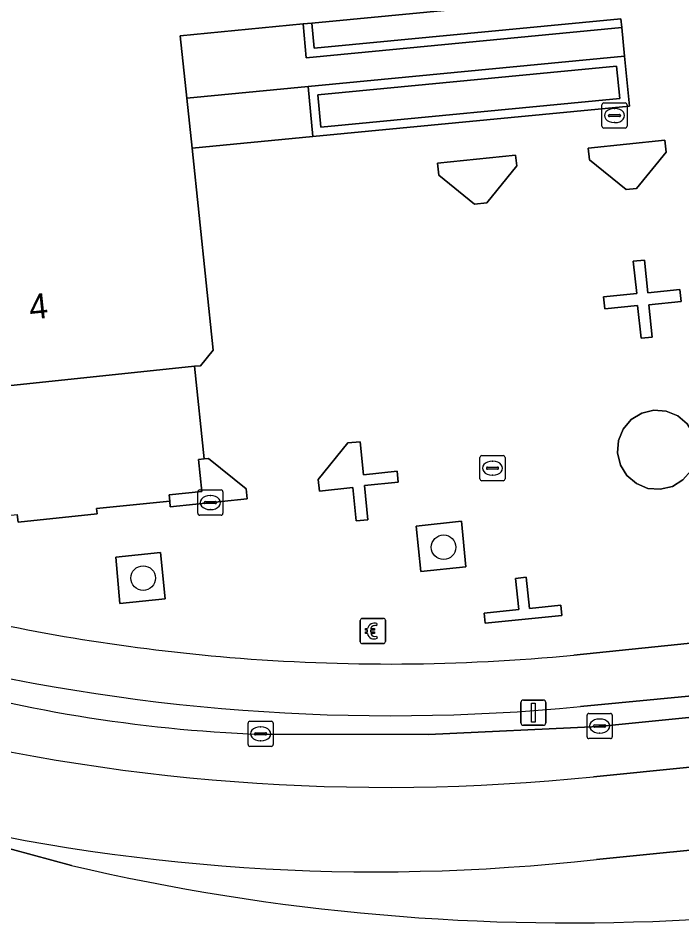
# Model space of a CAD drawing. Extents: x 160675 to 161153, y 383241 to 383714.
# Drawn here: x 160947.05 to 160973.43, y 383561.77 to 383597.73 of the extents above; entities that cross this region are included whole.
import ezdxf

# ---------------------------------------------------------------- set-up
doc = ezdxf.new("R2010")
doc.units = 0
for name, color, linetype in [('IMGEO_Berm_open', 7, 'Continuous'), ('IMGEO_Betaalautomaat', 7, 'Continuous'), ('IMGEO_Boom', 7, 'Continuous'), ('IMGEO_Fietspad_gesloten', 7, 'Continuous'), ('IMGEO_Grasland_overig', 7, 'Continuous'), ('IMGEO_Groenvoorziening', 7, 'Continuous'), ('IMGEO_Kolk', 7, 'Continuous'), ('IMGEO_Lichtmast', 7, 'Continuous'), ('IMGEO_Muur', 7, 'Continuous'), ('IMGEO_OVBaan_gesloten', 7, 'Continuous'), ('IMGEO_Pand', 7, 'Continuous'), ('IMGEO_Pand_nummerreeks', 7, 'Continuous'), ('IMGEO_Parkeervlak_open', 7, 'Continuous'), ('IMGEO_Rijbaan_lokaal_gesloten', 7, 'Continuous'), ('IMGEO_Terreindeel_gesloten', 7, 'Continuous'), ('IMGEO_Voetpad_open', 7, 'Continuous')]:
    doc.layers.add(name, color=color, linetype=linetype)

msp = doc.modelspace()

# ---------------------------------------------------------------- linework, layer by layer
at = {"layer": 'IMGEO_Berm_open'}
for points in [[(160942.181, 383566.161), (160883.368, 383582.463), (160880.432, 383583.23), (160880.388, 383583.018), (160942.127, 383565.955), (160949.177, 383564.05)], [(160977.449, 383568.326), (160978.106, 383568.424), (160978.543, 383571.243), (160969.402, 383570.361)], [(160956.662, 383569.267), (160963.365, 383569.248), (160970.137, 383569.576), (160974.363, 383569.996)], [(160977.669, 383564.976), (160976.009, 383564.886), (160970.034, 383564.292)]]:
    msp.add_lwpolyline(points, dxfattribs=at)
for centre, radius, start, end in [((160961.872, 383648.668), 78.668, 255.91174, 275.49255), ((160958.774, 383626.604), 57.376, 253.39085, 267.89005), ((160961.248, 383641.837), 78.041, 255.85815, 276.46401), ((160968.982, 383648.752), 86.987, 256.83983, 273.19843)]:
    msp.add_arc(centre, radius, start, end, dxfattribs=at)
at = {"layer": 'IMGEO_Betaalautomaat'}
for p, q in [((160960.648, 383572.943), (160960.648, 383573.784)), ((160960.648, 383573.784), (160960.648, 383572.943)), ((160960.723, 383573.867), (160961.564, 383573.867)), ((160961.564, 383573.867), (160960.723, 383573.867)), ((160961.31, 383573.672), (160961.293, 383573.572)), ((160961.647, 383573.793), (160961.647, 383572.952)), ((160961.647, 383572.952), (160961.647, 383573.793)), ((160960.931, 383573.331), (160960.931, 383573.399)), ((160961.052, 383573.399), (160961.052, 383573.331)), ((160961.297, 383573.166), (160961.319, 383573.079)), ((160961.573, 383572.868), (160960.732, 383572.868)), ((160960.732, 383572.868), (160961.573, 383572.868))]:
    msp.add_line(p, q, dxfattribs=at)
for points in [[(160960.931, 383573.399), (160960.862, 383573.399), (160960.862, 383573.468), (160960.941, 383573.468)], [(160960.936, 383573.262), (160960.862, 383573.262), (160960.862, 383573.331), (160960.931, 383573.331)], [(160961.063, 383573.468), (160961.21, 383573.468), (160961.21, 383573.399), (160961.052, 383573.399)], [(160961.052, 383573.331), (160961.21, 383573.331), (160961.21, 383573.262), (160961.066, 383573.262)]]:
    msp.add_lwpolyline(points, dxfattribs=at)
for centre, radius, start, end in [((160960.726, 383573.79), 0.0779, 92.4484, 184.2845), ((160960.726, 383573.79), 0.0779, 92.4484, 184.2845), ((160961.224, 383573.392), 0.293, 73.014, 165.0139), ((160961.57, 383573.79), 0.0779, 2.4484, 94.2845), ((160961.57, 383573.79), 0.0779, 2.4484, 94.2845), ((160961.23, 383573.405), 0.179, 69.3236, 159.5683), ((160960.726, 383572.946), 0.0779, 182.4484, 274.2845), ((160960.726, 383572.946), 0.0779, 182.4484, 274.2845), ((160961.197, 383573.317), 0.267, 191.8096, 297.0389), ((160961.23, 383573.332), 0.179, 202.7625, 291.8693), ((160961.57, 383572.946), 0.0779, 272.4484, 4.2845), ((160961.57, 383572.946), 0.0779, 272.4484, 4.2845)]:
    msp.add_arc(centre, radius, start, end, dxfattribs=at)
at = {"layer": 'IMGEO_Boom'}
for centre in [(160963.959, 383576.696), (160952.022, 383575.472)]:
    msp.add_circle(centre, 0.489, dxfattribs=at)
at = {"layer": 'IMGEO_Fietspad_gesloten'}
for points in [[(160978.543, 383571.243), (160980.974, 383571.474), (160985.089, 383571.866), (160985.132, 383571.87), (160986.514, 383574.193), (160969.142, 383572.409)], [(160969.402, 383570.361), (160978.543, 383571.243)]]:
    msp.add_lwpolyline(points, dxfattribs=at)
for centre, radius, start, end in [((160961.787, 383648.532), 76.474, 256.41726, 265.25743), ((160961.872, 383648.668), 78.668, 255.91174, 275.49255), ((160961.809, 383648.263), 76.207, 265.22393, 275.52169)]:
    msp.add_arc(centre, radius, start, end, dxfattribs=at)
at = {"layer": 'IMGEO_Grasland_overig'}
msp.add_lwpolyline([(160970.959, 383594.533), (160970.835, 383595.824), (160958.96, 383594.683), (160959.084, 383593.393)], close=True, dxfattribs=at)
at = {"layer": 'IMGEO_Groenvoorziening'}
msp.add_lwpolyline([(160923.625, 383582.077), (160943.059, 383576.719), (160943.007, 383577.314), (160944.295, 383577.422), (160944.303, 383577.711), (160947.02, 383577.997), (160947.052, 383577.699), (160950.193, 383578.027), (160950.172, 383578.233), (160953.077, 383578.527), (160953.051, 383578.774), (160954.349, 383578.909), (160954.216, 383580.184), (160954.439, 383580.207), (160954.067, 383583.889), (160941.844, 383582.612), (160941.315, 383583.041), (160940.741, 383588.532), (160905.51, 383584.853), (160905.714, 383584.622)], dxfattribs=at)
for points in [[(160964.847, 383575.924), (160964.677, 383577.729), (160962.874, 383577.535), (160963.06, 383575.731)], [(160952.9, 383574.652), (160952.714, 383576.485), (160950.932, 383576.3), (160951.098, 383574.461)]]:
    msp.add_lwpolyline(points, close=True, dxfattribs=at)
at = {"layer": 'IMGEO_Kolk'}
for p, q in [((160970.254, 383593.429), (160970.254, 383594.281)), ((160970.329, 383594.355), (160971.181, 383594.355)), ((160971.255, 383594.281), (160971.255, 383593.429)), ((160970.513, 383593.849), (160970.513, 383593.861)), ((160970.951, 383593.812), (160970.553, 383593.812)), ((160970.556, 383593.898), (160970.954, 383593.898)), ((160970.742, 383594.135), (160970.767, 383594.135)), ((160970.997, 383593.861), (160970.997, 383593.849)), ((160970.765, 383593.575), (160970.74, 383593.575)), ((160971.181, 383593.355), (160970.329, 383593.355)), ((160965.405, 383579.414), (160965.405, 383580.266)), ((160965.48, 383580.34), (160966.332, 383580.34)), ((160966.406, 383580.266), (160966.406, 383579.414)), ((160965.664, 383579.834), (160965.664, 383579.846)), ((160966.102, 383579.797), (160965.704, 383579.797)), ((160965.707, 383579.883), (160966.105, 383579.883)), ((160965.893, 383580.12), (160965.918, 383580.12)), ((160966.148, 383579.846), (160966.148, 383579.834)), ((160965.916, 383579.56), (160965.891, 383579.56)), ((160966.332, 383579.34), (160965.48, 383579.34)), ((160954.192, 383578.046), (160954.192, 383578.898)), ((160954.267, 383578.972), (160955.119, 383578.972)), ((160954.68, 383578.752), (160954.705, 383578.752)), ((160955.193, 383578.898), (160955.193, 383578.046)), ((160954.451, 383578.466), (160954.451, 383578.478)), ((160954.889, 383578.429), (160954.491, 383578.429)), ((160954.494, 383578.515), (160954.892, 383578.515)), ((160954.935, 383578.478), (160954.935, 383578.466)), ((160955.119, 383577.972), (160954.267, 383577.972)), ((160954.703, 383578.192), (160954.678, 383578.192)), ((160969.738, 383570.09), (160970.59, 383570.09)), ((160956.188, 383568.854), (160956.188, 383569.706)), ((160956.263, 383569.78), (160957.115, 383569.78)), ((160957.189, 383569.706), (160957.189, 383568.854)), ((160969.663, 383569.164), (160969.663, 383570.016)), ((160970.151, 383569.87), (160970.176, 383569.87)), ((160970.664, 383570.016), (160970.664, 383569.164)), ((160956.676, 383569.56), (160956.701, 383569.56)), ((160969.922, 383569.584), (160969.922, 383569.596)), ((160970.36, 383569.547), (160969.962, 383569.547)), ((160969.965, 383569.633), (160970.363, 383569.633)), ((160970.406, 383569.596), (160970.406, 383569.584)), ((160956.447, 383569.274), (160956.447, 383569.286)), ((160956.885, 383569.237), (160956.487, 383569.237)), ((160956.49, 383569.323), (160956.888, 383569.323)), ((160956.699, 383569), (160956.674, 383569)), ((160956.931, 383569.286), (160956.931, 383569.274)), ((160970.59, 383569.09), (160969.738, 383569.09)), ((160970.174, 383569.31), (160970.149, 383569.31)), ((160957.115, 383568.78), (160956.263, 383568.78))]:
    msp.add_line(p, q, dxfattribs=at)
for points in [[(160970.254, 383593.429), (160970.254, 383594.281)], [(160970.329, 383594.355), (160971.181, 383594.355)], [(160971.255, 383594.281), (160971.255, 383593.429)], [(160971.181, 383593.355), (160970.329, 383593.355)], [(160965.405, 383579.414), (160965.405, 383580.266)], [(160965.48, 383580.34), (160966.332, 383580.34)], [(160966.406, 383580.266), (160966.406, 383579.414)], [(160966.332, 383579.34), (160965.48, 383579.34)], [(160954.192, 383578.046), (160954.192, 383578.898)], [(160954.267, 383578.972), (160955.119, 383578.972)], [(160955.193, 383578.898), (160955.193, 383578.046)], [(160955.119, 383577.972), (160954.267, 383577.972)], [(160969.738, 383570.09), (160970.59, 383570.09)], [(160956.188, 383568.854), (160956.188, 383569.706)], [(160956.263, 383569.78), (160957.115, 383569.78)], [(160957.189, 383569.706), (160957.189, 383568.854)], [(160969.663, 383569.164), (160969.663, 383570.016)], [(160970.664, 383570.016), (160970.664, 383569.164)], [(160970.59, 383569.09), (160969.738, 383569.09)], [(160957.115, 383568.78), (160956.263, 383568.78)]]:
    msp.add_lwpolyline(points, dxfattribs=at)
for centre, radius, start, end in [((160970.331, 383594.279), 0.0765, 91.552, 178.448), ((160970.331, 383594.279), 0.0765, 91.552, 178.448), ((160971.179, 383594.279), 0.0765, 1.552, 88.448), ((160971.179, 383594.279), 0.0765, 1.552, 88.448), ((160970.553, 383593.858), 0.0403, 85.8775, 175.7526), ((160970.55, 383593.848), 0.0366, 178.938, 274.7102), ((160970.954, 383593.855), 0.043, 264.8664, 352.4533), ((160970.958, 383593.86), 0.0386, 1.7309, 96.639), ((160970.331, 383593.431), 0.0765, 181.552, 268.448), ((160970.331, 383593.431), 0.0765, 181.552, 268.448), ((160971.179, 383593.431), 0.0765, 271.552, 358.448), ((160971.179, 383593.431), 0.0765, 271.552, 358.448), ((160965.482, 383580.264), 0.0765, 91.552, 178.448), ((160965.482, 383580.264), 0.0765, 91.552, 178.448), ((160966.33, 383580.264), 0.0765, 1.552, 88.448), ((160966.33, 383580.264), 0.0765, 1.552, 88.448), ((160965.704, 383579.843), 0.0403, 85.8775, 175.7526), ((160965.701, 383579.833), 0.0366, 178.938, 274.7102), ((160966.105, 383579.84), 0.043, 264.8664, 352.4533), ((160966.109, 383579.845), 0.0386, 1.7309, 96.639), ((160965.482, 383579.416), 0.0765, 181.552, 268.448), ((160965.482, 383579.416), 0.0765, 181.552, 268.448), ((160966.33, 383579.416), 0.0765, 271.552, 358.448), ((160966.33, 383579.416), 0.0765, 271.552, 358.448), ((160954.269, 383578.896), 0.0765, 91.552, 178.448), ((160954.269, 383578.896), 0.0765, 91.552, 178.448), ((160955.117, 383578.896), 0.0765, 1.552, 88.448), ((160955.117, 383578.896), 0.0765, 1.552, 88.448), ((160954.491, 383578.475), 0.0403, 85.8775, 175.7526), ((160954.488, 383578.465), 0.0366, 178.938, 274.7102), ((160954.892, 383578.472), 0.043, 264.8664, 352.4533), ((160954.896, 383578.477), 0.0386, 1.7309, 96.639), ((160954.269, 383578.048), 0.0765, 181.552, 268.448), ((160954.269, 383578.048), 0.0765, 181.552, 268.448), ((160955.117, 383578.048), 0.0765, 271.552, 358.448), ((160955.117, 383578.048), 0.0765, 271.552, 358.448), ((160969.74, 383570.014), 0.0765, 91.552, 178.448), ((160969.74, 383570.014), 0.0765, 91.552, 178.448), ((160970.588, 383570.014), 0.0765, 1.552, 88.448), ((160970.588, 383570.014), 0.0765, 1.552, 88.448), ((160956.265, 383569.704), 0.0765, 91.552, 178.448), ((160956.265, 383569.704), 0.0765, 91.552, 178.448), ((160957.113, 383569.704), 0.0765, 1.552, 88.448), ((160957.113, 383569.704), 0.0765, 1.552, 88.448), ((160969.962, 383569.593), 0.0403, 85.8775, 175.7526), ((160969.959, 383569.583), 0.0366, 178.938, 274.7102), ((160970.363, 383569.59), 0.043, 264.8664, 352.4533), ((160970.367, 383569.595), 0.0386, 1.7309, 96.639), ((160956.487, 383569.283), 0.0403, 85.8775, 175.7526), ((160956.484, 383569.273), 0.0366, 178.938, 274.7102), ((160956.888, 383569.28), 0.043, 264.8664, 352.4533), ((160956.892, 383569.285), 0.0386, 1.7309, 96.639), ((160969.74, 383569.166), 0.0765, 181.552, 268.448), ((160969.74, 383569.166), 0.0765, 181.552, 268.448), ((160970.588, 383569.166), 0.0765, 271.552, 358.448), ((160970.588, 383569.166), 0.0765, 271.552, 358.448), ((160956.265, 383568.856), 0.0765, 181.552, 268.448), ((160956.265, 383568.856), 0.0765, 181.552, 268.448), ((160957.113, 383568.856), 0.0765, 271.552, 358.448), ((160957.113, 383568.856), 0.0765, 271.552, 358.448)]:
    msp.add_arc(centre, radius, start, end, dxfattribs=at)
for centre, major_axis, ratio, start_param, end_param in [((160970.741, 383593.855), (-0.387, 0.002), 0.722429, 4.712389, 7.853982), ((160970.766, 383593.855), (-0.39, 0.002), 0.717154, 1.570796, 4.712389), ((160965.892, 383579.84), (-0.387, 0.002), 0.722429, 4.712389, 7.853982), ((160965.917, 383579.84), (-0.39, 0.002), 0.717154, 1.570796, 4.712389), ((160954.679, 383578.472), (-0.387, 0.002), 0.722429, 4.712389, 7.853982), ((160954.704, 383578.472), (-0.39, 0.002), 0.717154, 1.570796, 4.712389), ((160970.15, 383569.59), (-0.387, 0.002), 0.722429, 4.712389, 7.853982), ((160970.175, 383569.59), (-0.39, 0.002), 0.717154, 1.570796, 4.712389), ((160956.675, 383569.28), (-0.387, 0.002), 0.722429, 4.712389, 7.853982), ((160956.7, 383569.28), (-0.39, 0.002), 0.717154, 1.570796, 4.712389)]:
    msp.add_ellipse(centre, major_axis=major_axis, ratio=ratio, start_param=start_param, end_param=end_param, dxfattribs=at)
at = {"layer": 'IMGEO_Lichtmast'}
for p, q in [((160967.032, 383569.72), (160967.032, 383570.52)), ((160967.032, 383570.52), (160967.032, 383569.72)), ((160967.132, 383570.62), (160967.922, 383570.62)), ((160967.922, 383570.62), (160967.132, 383570.62)), ((160968.022, 383570.52), (160968.022, 383569.72)), ((160968.022, 383569.72), (160968.022, 383570.52)), ((160967.922, 383569.62), (160967.132, 383569.62)), ((160967.132, 383569.62), (160967.922, 383569.62))]:
    msp.add_line(p, q, dxfattribs=at)
msp.add_lwpolyline([(160967.452, 383570.495), (160967.602, 383570.495), (160967.602, 383569.745), (160967.452, 383569.745), (160967.452, 383570.495)], dxfattribs=at)
for centre, start, end in [((160967.132, 383570.52), 90, 180), ((160967.132, 383570.52), 90, 180), ((160967.922, 383570.52), 0, 90), ((160967.922, 383570.52), 360, 90), ((160967.132, 383569.72), 180, 270), ((160967.132, 383569.72), 180, 270), ((160967.922, 383569.72), 270, 0), ((160967.922, 383569.72), 270, 0)]:
    msp.add_arc(centre, 0.1, start, end, dxfattribs=at)
at = {"layer": 'IMGEO_Muur'}
for points in [[(160971.011, 383597.701), (160958.822, 383596.53), (160958.725, 383597.531), (160958.375, 383597.497), (160958.504, 383596.148), (160971.045, 383597.352)], [(160971.154, 383596.216), (160958.576, 383595.009), (160958.768, 383593.017), (160971.345, 383594.225)], [(160959.084, 383593.393), (160958.96, 383594.683), (160970.835, 383595.824), (160970.959, 383594.533)], [(160971.215, 383590.917), (160971.633, 383590.96), (160972.8, 383592.399), (160972.75, 383592.874), (160969.713, 383592.557), (160969.761, 383592.096)], [(160965.184, 383590.33), (160965.676, 383590.382), (160966.869, 383591.854), (160966.825, 383592.283), (160963.717, 383591.958), (160963.767, 383591.48)], [(160971.81, 383585.003), (160972.256, 383585.049), (160972.121, 383586.337), (160973.396, 383586.47), (160973.347, 383586.943), (160972.075, 383586.81), (160971.939, 383588.113), (160971.501, 383588.067), (160971.635, 383586.786), (160970.315, 383586.648), (160970.365, 383586.17), (160971.673, 383586.307)], [(160960.487, 383577.743), (160960.955, 383577.792), (160960.814, 383579.145), (160962.156, 383579.285), (160962.11, 383579.718), (160960.779, 383579.579), (160960.642, 383580.893), (160960.149, 383580.842), (160958.975, 383579.394), (160959.023, 383578.932), (160960.348, 383579.07)], [(160954.439, 383580.207), (160954.216, 383580.184), (160954.349, 383578.909), (160953.051, 383578.774), (160953.077, 383578.527), (160953.1, 383578.307), (160956.158, 383578.626), (160956.118, 383579.015), (160954.624, 383580.226)], [(160968.661, 383573.989), (160968.62, 383574.389), (160967.373, 383574.26), (160967.244, 383575.505), (160966.816, 383575.46), (160966.945, 383574.216), (160965.569, 383574.073), (160965.61, 383573.673)]]:
    msp.add_lwpolyline(points, close=True, dxfattribs=at)
at = {"layer": 'IMGEO_OVBaan_gesloten'}
msp.add_lwpolyline([(160949.177, 383564.05), (160942.127, 383565.955), (160880.388, 383583.018), (160880.346, 383582.924), (160861.613, 383588.006), (160783.094, 383609.33)], dxfattribs=at)
msp.add_arc((160968.982, 383648.752), 86.987, 256.83983, 273.19843, dxfattribs=at)
at = {"layer": 'IMGEO_Pand'}
msp.add_lwpolyline([(160941.844, 383582.612), (160954.067, 383583.889), (160954.3, 383583.913), (160954.803, 383584.533), (160953.965, 383592.556), (160953.757, 383594.546), (160953.498, 383597.029), (160958.375, 383597.497), (160958.725, 383597.531), (160970.915, 383598.702), (160976.95, 383599.281), (160977.373, 383599.821), (160976.624, 383606.987), (160980.279, 383607.369), (160979.633, 383613.553), (160978.737, 383614.28), (160975.885, 383613.983), (160975.232, 383620.235), (160974.675, 383620.687), (160933.46, 383616.382)], dxfattribs=at)
at = {"layer": 'IMGEO_Parkeervlak_open'}
for points in [[(160974.363, 383569.996), (160970.137, 383569.576), (160963.365, 383569.248), (160956.662, 383569.267)], [(160969.92, 383567.575), (160977.449, 383568.326)]]:
    msp.add_lwpolyline(points, dxfattribs=at)
for centre, radius, start, end in [((160958.774, 383626.604), 57.376, 253.39085, 267.89005), ((160961.705, 383647.262), 80.11, 255.44106, 275.88609)]:
    msp.add_arc(centre, radius, start, end, dxfattribs=at)
at = {"layer": 'IMGEO_Rijbaan_lokaal_gesloten'}
msp.add_lwpolyline([(160970.034, 383564.292), (160976.009, 383564.886), (160977.669, 383564.976), (160978.106, 383568.424), (160977.449, 383568.326), (160969.92, 383567.575)], dxfattribs=at)
for centre, radius, start, end in [((160961.705, 383647.262), 80.11, 255.44106, 275.88609), ((160961.248, 383641.837), 78.041, 255.85815, 276.46401)]:
    msp.add_arc(centre, radius, start, end, dxfattribs=at)
at = {"layer": 'IMGEO_Terreindeel_gesloten'}
msp.add_lwpolyline([(160972.574, 383578.999), (160973.054, 383579.115), (160973.474, 383579.374), (160973.794, 383579.75), (160973.982, 383580.207), (160974.02, 383580.699), (160973.904, 383581.179), (160973.645, 383581.599), (160973.269, 383581.919), (160972.812, 383582.107), (160972.32, 383582.145), (160971.84, 383582.029), (160971.42, 383581.77), (160971.1, 383581.394), (160970.912, 383580.937), (160970.874, 383580.445), (160970.99, 383579.965), (160971.249, 383579.545), (160971.625, 383579.225), (160972.082, 383579.037)], close=True, dxfattribs=at)
at = {"layer": 'IMGEO_Voetpad_open'}
for points in [[(160970.915, 383598.702), (160958.725, 383597.531), (160958.822, 383596.53), (160971.011, 383597.701), (160971.045, 383597.352), (160971.154, 383596.216), (160971.345, 383594.225), (160958.768, 383593.017), (160953.965, 383592.556), (160954.803, 383584.533), (160954.3, 383583.913), (160954.067, 383583.889), (160954.439, 383580.207), (160954.624, 383580.226), (160956.118, 383579.015), (160956.158, 383578.626), (160953.1, 383578.307), (160953.077, 383578.527), (160950.172, 383578.233), (160950.193, 383578.027), (160947.052, 383577.699), (160947.02, 383577.997)], [(160969.142, 383572.409), (160986.514, 383574.193), (160986.573, 383575.26), (160986.543, 383576.133), (160986.162, 383579.582), (160985.113, 383589.719), (160984.769, 383593.047)]]:
    msp.add_lwpolyline(points, dxfattribs=at)
for points in [[(160958.576, 383595.009), (160971.154, 383596.216), (160971.045, 383597.352), (160958.504, 383596.148), (160958.375, 383597.497), (160953.498, 383597.029), (160953.757, 383594.546)], [(160958.576, 383595.009), (160953.757, 383594.546), (160953.965, 383592.556), (160958.768, 383593.017)], [(160971.215, 383590.917), (160969.761, 383592.096), (160969.713, 383592.557), (160972.75, 383592.874), (160972.8, 383592.399), (160971.633, 383590.96)], [(160963.767, 383591.48), (160963.717, 383591.958), (160966.825, 383592.283), (160966.869, 383591.854), (160965.676, 383590.382), (160965.184, 383590.33)], [(160971.673, 383586.307), (160970.365, 383586.17), (160970.315, 383586.648), (160971.635, 383586.786), (160971.501, 383588.067), (160971.939, 383588.113), (160972.075, 383586.81), (160973.347, 383586.943), (160973.396, 383586.47), (160972.121, 383586.337), (160972.256, 383585.049), (160971.81, 383585.003)], [(160970.912, 383580.937), (160971.1, 383581.394), (160971.42, 383581.77), (160971.84, 383582.029), (160972.32, 383582.145), (160972.812, 383582.107), (160973.269, 383581.919), (160973.645, 383581.599), (160973.904, 383581.179), (160974.02, 383580.699), (160973.982, 383580.207), (160973.794, 383579.75), (160973.474, 383579.374), (160973.054, 383579.115), (160972.574, 383578.999), (160972.082, 383579.037), (160971.625, 383579.225), (160971.249, 383579.545), (160970.99, 383579.965), (160970.874, 383580.445)], [(160960.642, 383580.893), (160960.779, 383579.579), (160962.11, 383579.718), (160962.156, 383579.285), (160960.814, 383579.145), (160960.955, 383577.792), (160960.487, 383577.743), (160960.348, 383579.07), (160959.023, 383578.932), (160958.975, 383579.394), (160960.149, 383580.842)], [(160964.677, 383577.729), (160964.847, 383575.924), (160963.06, 383575.731), (160962.874, 383577.535)], [(160952.714, 383576.485), (160952.9, 383574.652), (160951.098, 383574.461), (160950.932, 383576.3)], [(160968.62, 383574.389), (160968.661, 383573.989), (160965.61, 383573.673), (160965.569, 383574.073), (160966.945, 383574.216), (160966.816, 383575.46), (160967.244, 383575.505), (160967.373, 383574.26)]]:
    msp.add_lwpolyline(points, close=True, dxfattribs=at)
for centre, radius, start, end in [((160961.787, 383648.532), 76.474, 256.41726, 265.25743), ((160961.809, 383648.263), 76.207, 265.22393, 275.52169)]:
    msp.add_arc(centre, radius, start, end, dxfattribs=at)

# ---------------------------------------------------------------- texts
at = {"layer": 'IMGEO_Pand_nummerreeks'}
msp.add_text('4', height=1, rotation=5.9628, dxfattribs=at).set_placement((160947.537, 383585.74))

doc.saveas('drawing.dxf')
